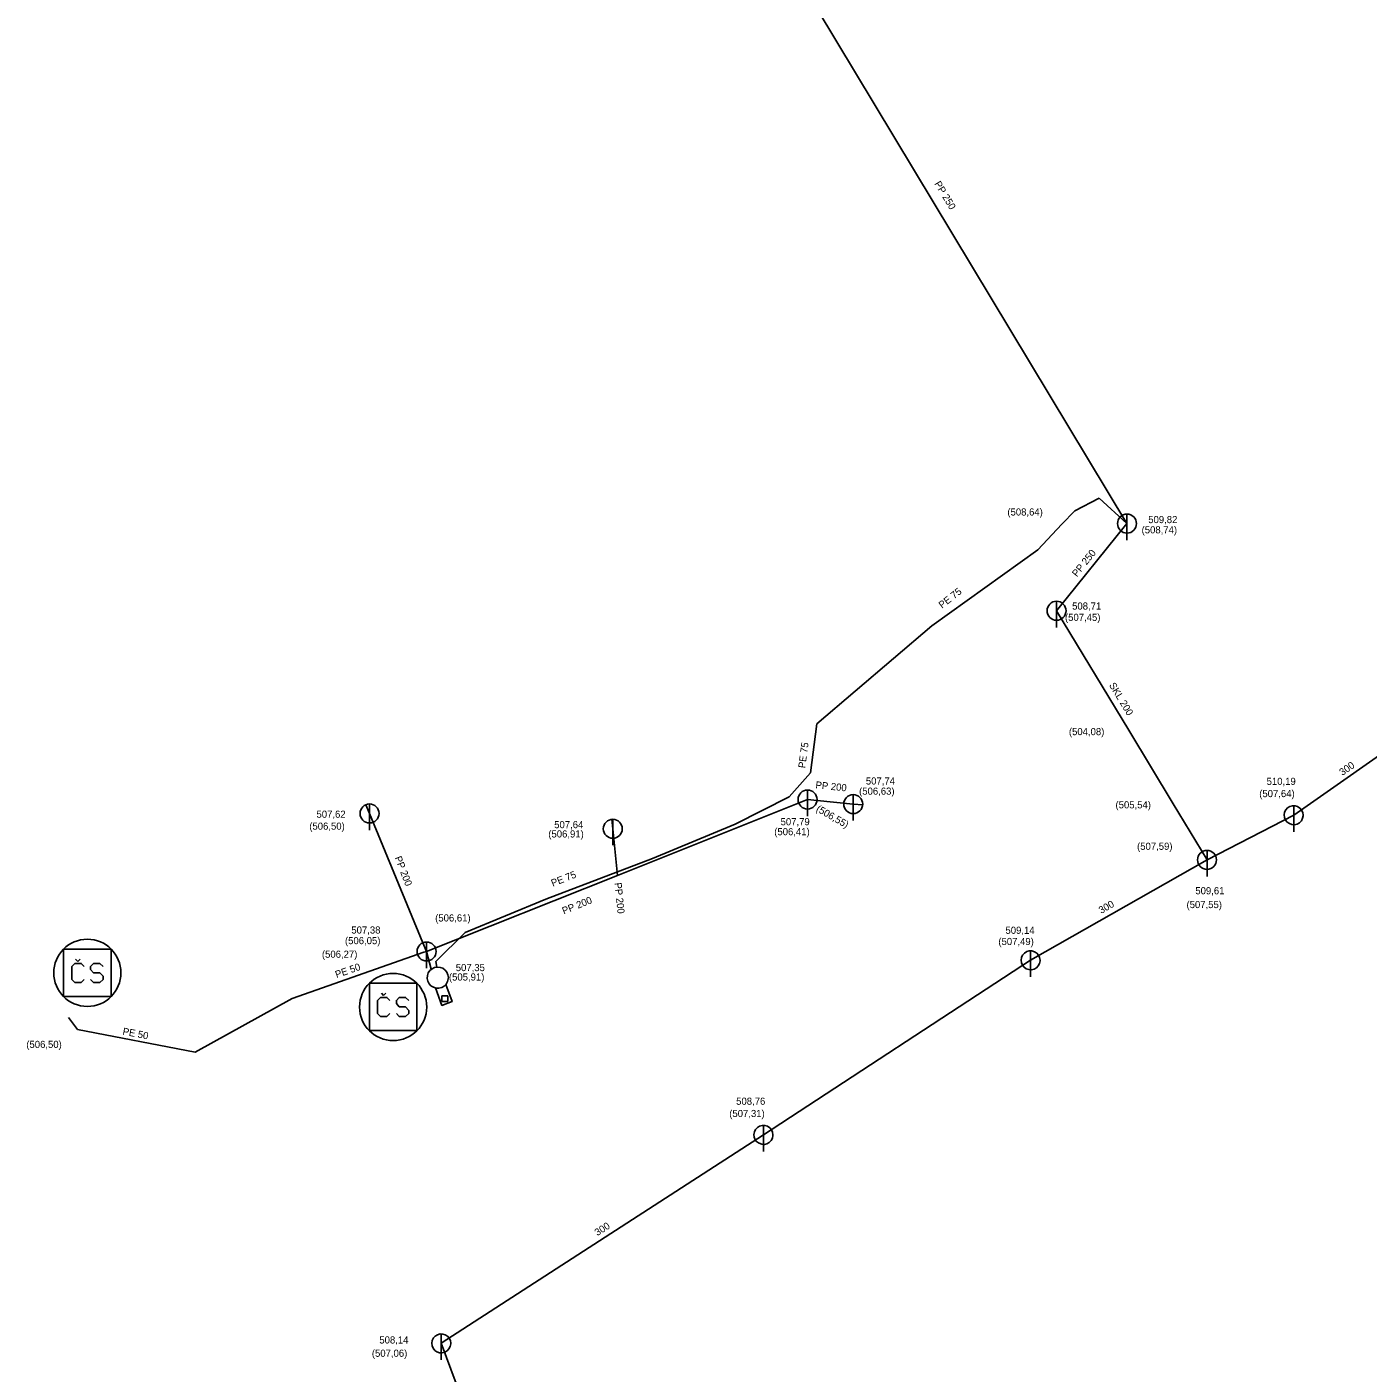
# Model space of a CAD drawing. Extents: x -476058 to -471893, y -1155786 to -1152000.
# Drawn here: x -475199.9 to -475058.6, y -1154216.9 to -1154075.1 of the extents above; entities that cross this region are included whole.
import ezdxf

# ---------------------------------------------------------------- set-up
doc = ezdxf.new("R2010")
doc.units = 0
for name, color, linetype in [('Vrstva 10', 7, 'Continuous'), ('Vrstva 11', 7, 'Continuous'), ('Vrstva 13', 7, 'Continuous'), ('Vrstva 17', 7, 'Continuous'), ('Vrstva 18', 7, 'Continuous'), ('Vrstva 19', 7, 'Continuous'), ('Vrstva 22', 7, 'Continuous'), ('Vrstva 23', 7, 'Continuous'), ('Vrstva 3', 7, 'Continuous'), ('Vrstva 4', 7, 'Continuous'), ('Vrstva 40', 7, 'Continuous'), ('Vrstva 45', 7, 'Continuous'), ('Vrstva 50', 7, 'Continuous')]:
    doc.layers.add(name, color=color, linetype=linetype)

msp = doc.modelspace()

# ---------------------------------------------------------------- linework, layer by layer
at = {"layer": 'Vrstva 10'}
for p, q in [((-475084.02, -1154126.4), (-475084.02, -1154129.14)), ((-475091.44, -1154135.58), (-475091.44, -1154138.33)), ((-475117.67, -1154155.47), (-475117.67, -1154158.21)), ((-475112.86, -1154155.95), (-475112.86, -1154158.69)), ((-475163.81, -1154156.94), (-475163.81, -1154159.69)), ((-475066.46, -1154157.12), (-475066.46, -1154159.87)), ((-475138.19, -1154158.55), (-475138.19, -1154161.29)), ((-475075.59, -1154161.83), (-475075.59, -1154164.58)), ((-475157.8, -1154171.48), (-475157.8, -1154174.23)), ((-475094.18, -1154172.41), (-475094.18, -1154175.16)), ((-475122.32, -1154190.8), (-475122.32, -1154193.55)), ((-475156.26, -1154212.76), (-475156.26, -1154215.51))]:
    msp.add_line(p, q, dxfattribs=at)
for points in [[(-475065.46, -1154158.12), (-475065.5, -1154157.84), (-475065.62, -1154157.58), (-475065.8, -1154157.37), (-475066.04, -1154157.22), (-475066.3, -1154157.13), (-475066.59, -1154157.13), (-475066.86, -1154157.2), (-475067.1, -1154157.35), (-475067.29, -1154157.56), (-475067.41, -1154157.81), (-475067.46, -1154158.09), (-475067.43, -1154158.37), (-475067.32, -1154158.63), (-475067.14, -1154158.85), (-475066.91, -1154159.01), (-475066.64, -1154159.1), (-475066.36, -1154159.12), (-475066.09, -1154159.05), (-475065.84, -1154158.91), (-475065.65, -1154158.7), (-475065.52, -1154158.45), (-475065.46, -1154158.18), (-475065.46, -1154158.12)], [(-475093.18, -1154173.41), (-475093.22, -1154173.13), (-475093.34, -1154172.87), (-475093.52, -1154172.66), (-475093.76, -1154172.51), (-475094.03, -1154172.42), (-475094.31, -1154172.42), (-475094.58, -1154172.49), (-475094.82, -1154172.64), (-475095.01, -1154172.85), (-475095.13, -1154173.1), (-475095.18, -1154173.38), (-475095.15, -1154173.66), (-475095.04, -1154173.92), (-475094.86, -1154174.14), (-475094.63, -1154174.3), (-475094.36, -1154174.39), (-475094.08, -1154174.41), (-475093.81, -1154174.34), (-475093.56, -1154174.2), (-475093.37, -1154173.99), (-475093.24, -1154173.74), (-475093.18, -1154173.47), (-475093.18, -1154173.41)], [(-475121.32, -1154191.8), (-475121.36, -1154191.52), (-475121.48, -1154191.26), (-475121.66, -1154191.05), (-475121.9, -1154190.9), (-475122.17, -1154190.81), (-475122.45, -1154190.81), (-475122.72, -1154190.88), (-475122.96, -1154191.03), (-475123.15, -1154191.24), (-475123.27, -1154191.49), (-475123.32, -1154191.77), (-475123.29, -1154192.05), (-475123.18, -1154192.31), (-475123, -1154192.53), (-475122.77, -1154192.69), (-475122.5, -1154192.78), (-475122.22, -1154192.8), (-475121.95, -1154192.73), (-475121.7, -1154192.59), (-475121.51, -1154192.38), (-475121.38, -1154192.13), (-475121.32, -1154191.86), (-475121.32, -1154191.8)], [(-475155.26, -1154213.76), (-475155.3, -1154213.48), (-475155.42, -1154213.23), (-475155.6, -1154213.01), (-475155.83, -1154212.86), (-475156.1, -1154212.78), (-475156.39, -1154212.77), (-475156.66, -1154212.85), (-475156.9, -1154212.99), (-475157.09, -1154213.2), (-475157.21, -1154213.46), (-475157.26, -1154213.74), (-475157.23, -1154214.02), (-475157.12, -1154214.28), (-475156.94, -1154214.5), (-475156.71, -1154214.66), (-475156.44, -1154214.75), (-475156.16, -1154214.76), (-475155.89, -1154214.69), (-475155.64, -1154214.55), (-475155.45, -1154214.35), (-475155.32, -1154214.1), (-475155.26, -1154213.82), (-475155.26, -1154213.76)]]:
    msp.add_lwpolyline(points, dxfattribs=at)
for centre in [(-475084.02, -1154127.4), (-475091.44, -1154136.58), (-475117.67, -1154156.47), (-475112.86, -1154156.95), (-475163.81, -1154157.94), (-475138.19, -1154159.55), (-475075.59, -1154162.83), (-475157.8, -1154172.48)]:
    msp.add_circle(centre, 1, dxfattribs=at)
at = {"layer": 'Vrstva 11'}
for p, q in [((-475196.04, -1154172.23), (-475191.04, -1154172.23)), ((-475196.04, -1154177.23), (-475196.04, -1154172.23)), ((-475191.04, -1154172.23), (-475191.04, -1154177.23)), ((-475163.83, -1154175.82), (-475158.83, -1154175.82)), ((-475163.83, -1154180.82), (-475163.83, -1154175.82)), ((-475158.83, -1154175.82), (-475158.83, -1154180.82)), ((-475191.04, -1154177.23), (-475196.04, -1154177.23)), ((-475158.83, -1154180.82), (-475163.83, -1154180.82))]:
    msp.add_line(p, q, dxfattribs=at)
for points in [[(-475193.86, -1154175.42), (-475194.19, -1154175.73), (-475194.85, -1154175.73), (-475195.17, -1154175.42), (-475195.17, -1154174.05), (-475194.85, -1154173.73), (-475194.19, -1154173.73), (-475193.86, -1154174.05)], [(-475194.54, -1154173.53), (-475194.78, -1154173.29)], [(-475194.54, -1154173.53), (-475194.3, -1154173.29)], [(-475193.2, -1154175.42), (-475192.89, -1154175.73), (-475192.23, -1154175.73), (-475191.89, -1154175.42), (-475191.89, -1154175.09), (-475192.23, -1154174.73), (-475192.89, -1154174.73), (-475193.2, -1154174.38), (-475193.2, -1154174.05), (-475192.89, -1154173.73), (-475192.23, -1154173.73), (-475191.89, -1154174.05)], [(-475161.66, -1154179.01), (-475161.99, -1154179.32), (-475162.65, -1154179.32), (-475162.96, -1154179.01), (-475162.96, -1154177.64), (-475162.65, -1154177.32), (-475161.99, -1154177.32), (-475161.66, -1154177.64)], [(-475162.33, -1154177.12), (-475162.57, -1154176.88)], [(-475162.33, -1154177.12), (-475162.1, -1154176.88)], [(-475160.99, -1154179.01), (-475160.68, -1154179.32), (-475160.02, -1154179.32), (-475159.69, -1154179.01), (-475159.69, -1154178.68), (-475160.02, -1154178.32), (-475160.68, -1154178.32), (-475160.99, -1154177.97), (-475160.99, -1154177.64), (-475160.68, -1154177.32), (-475160.02, -1154177.32), (-475159.69, -1154177.64)]]:
    msp.add_lwpolyline(points, dxfattribs=at)
for centre in [(-475193.54, -1154174.73), (-475161.33, -1154178.33)]:
    msp.add_circle(centre, 3.54, dxfattribs=at)
at = {"layer": 'Vrstva 13'}
for p, q in [((-475155.58, -1154177.14), (-475156.18, -1154177.14)), ((-475156.18, -1154177.14), (-475156.18, -1154177.74)), ((-475156.18, -1154177.74), (-475155.58, -1154177.74)), ((-475155.58, -1154177.74), (-475155.58, -1154177.14))]:
    msp.add_line(p, q, dxfattribs=at)
at = {"layer": 'Vrstva 22'}
msp.add_lwpolyline([(-475155.51, -1154175.23), (-475155.55, -1154174.94), (-475155.67, -1154174.66), (-475155.85, -1154174.43), (-475156.09, -1154174.25), (-475156.37, -1154174.15), (-475156.67, -1154174.12), (-475156.96, -1154174.17), (-475157.23, -1154174.29), (-475157.46, -1154174.49), (-475157.62, -1154174.74), (-475157.72, -1154175.02), (-475157.74, -1154175.31), (-475157.67, -1154175.61), (-475157.54, -1154175.87), (-475157.34, -1154176.09), (-475157.08, -1154176.25), (-475156.8, -1154176.33), (-475156.5, -1154176.34), (-475156.21, -1154176.27), (-475155.95, -1154176.12), (-475155.74, -1154175.91), (-475155.59, -1154175.65), (-475155.52, -1154175.36), (-475155.51, -1154175.23)], dxfattribs=at)
at = {"layer": 'Vrstva 23'}
msp.add_lwpolyline([(-475156.88, -1154176.32), (-475156.18, -1154178.16), (-475155.12, -1154177.75), (-475155.78, -1154175.96)], dxfattribs=at)
at = {"layer": 'Vrstva 40'}
for p, q in [((-475086.94, -1154124.71), (-475084.02, -1154127.4)), ((-475104.57, -1154138.17), (-475093.41, -1154130.15)), ((-475091.44, -1154136.58), (-475083.84, -1154149.15)), ((-475116.68, -1154148.49), (-475104.57, -1154138.17)), ((-475117.37, -1154153.65), (-475116.68, -1154148.49)), ((-475083.84, -1154149.15), (-475079.16, -1154156.91)), ((-475119.6, -1154156.2), (-475117.37, -1154153.65)), ((-475125.29, -1154159.05), (-475119.6, -1154156.2)), ((-475079.16, -1154156.91), (-475075.59, -1154162.83)), ((-475134, -1154162.68), (-475125.29, -1154159.05)), ((-475145.25, -1154166.95), (-475134, -1154162.68)), ((-475153.74, -1154170.48), (-475145.25, -1154166.95))]:
    msp.add_line(p, q, dxfattribs=at)
for points in [[(-475118.72, -1154069.74), (-475084.02, -1154127.4)], [(-475093.41, -1154130.15), (-475090.87, -1154127.47), (-475089.53, -1154126.04), (-475086.94, -1154124.71)], [(-475084.02, -1154127.4), (-475091.44, -1154136.58)], [(-475117.67, -1154156.47), (-475137.68, -1154164.47)], [(-475137.68, -1154164.47), (-475157.8, -1154172.48)], [(-475156.72, -1154174.12), (-475156.84, -1154173.54), (-475153.74, -1154170.48)], [(-475157.8, -1154172.48), (-475157.31, -1154174.35)]]:
    msp.add_lwpolyline(points, dxfattribs=at)
at = {"layer": 'Vrstva 45'}
for points in [[(-475053.57, -1154149.1), (-475066.46, -1154158.12)], [(-475066.46, -1154158.12), (-475075.59, -1154162.83)], [(-475075.59, -1154162.83), (-475094.18, -1154173.41)], [(-475094.18, -1154173.41), (-475122.32, -1154191.8)], [(-475122.32, -1154191.8), (-475156.26, -1154213.76)], [(-475156.26, -1154213.76), (-475150.39, -1154229.5)]]:
    msp.add_lwpolyline(points, dxfattribs=at)
at = {"layer": 'Vrstva 50'}
for points in [[(-475111.86, -1154157.04), (-475112.86, -1154156.95), (-475116.67, -1154156.56), (-475117.67, -1154156.47)], [(-475164.2, -1154157.02), (-475163.81, -1154157.94), (-475158.19, -1154171.56), (-475157.8, -1154172.48)], [(-475138.29, -1154158.55), (-475138.19, -1154159.55), (-475137.68, -1154164.47)], [(-475195.54, -1154179.44), (-475194.57, -1154180.69), (-475182.2, -1154183.07), (-475171.96, -1154177.44), (-475158.11, -1154172.56)], [(-475158.11, -1154172.56), (-475157.8, -1154172.48)]]:
    msp.add_lwpolyline(points, dxfattribs=at)

# ---------------------------------------------------------------- texts
at = {"layer": 'Vrstva 17'}
for s, rotation, p in [('PP 250', 301.035, (-475104.34, -1154091.59)), ('PP 250', 51.062, (-475089.3, -1154133.07)), ('PE 75', 38.2319, (-475103.5, -1154136.38)), ('SKL 200', 301.1252, (-475085.94, -1154144.42)), ('PE 75', 82.4235, (-475117.92, -1154153.2)), ('PE 75', 21.5533, (-475144.51, -1154165.66)), ('PP 200', 21.7926, (-475143.35, -1154168.58))]:
    msp.add_text(s, height=0.75, rotation=rotation, dxfattribs=at).set_placement(p)
at = {"layer": 'Vrstva 18'}
for rotation, p in [(34.9831, (-475061.33, -1154153.99)), (29.6439, (-475086.74, -1154168.53)), (32.7753, (-475139.81, -1154202.48))]:
    msp.add_text('300 ', height=0.75, rotation=rotation, dxfattribs=at).set_placement(p)
at = {"layer": 'Vrstva 19'}
for s, rotation, p in [('PP 200', 354.2929, (-475116.86, -1154155.29)), ('PP 200', 291.1662, (-475161.18, -1154162.6)), ('PP 200', 275.8708, (-475138.01, -1154165.26)), ('PE 50', 19.145, (-475167.28, -1154175.29)), ('PE 50', 349.1253, (-475189.87, -1154181.23))]:
    msp.add_text(s, height=0.75, rotation=rotation, dxfattribs=at).set_placement(p)
at = {"layer": 'Vrstva 3'}
for s, p in [('509,82', (-475081.78, -1154127.35)), ('508,71', (-475089.8, -1154136.46)), ('507,74', (-475111.53, -1154154.89)), ('510,19', (-475069.31, -1154154.93)), ('507,62', (-475169.4, -1154158.39)), ('507,64', (-475144.36, -1154159.49)), ('507,79', (-475120.51, -1154159.18)), ('509,61', (-475076.82, -1154166.45)), ('507,38', (-475165.73, -1154170.59)), ('509,14', (-475096.82, -1154170.62)), ('507,35', (-475154.73, -1154174.55)), ('508,76', (-475125.19, -1154188.63)), ('508,14', (-475162.78, -1154213.78))]:
    msp.add_text(s, height=0.75, dxfattribs=at).set_placement(p)
at = {"layer": 'Vrstva 4'}
for s, p in [('(508,64)', (-475096.62, -1154126.55)), ('(508,74)', (-475082.48, -1154128.43)), ('(507,45)', (-475090.55, -1154137.65)), ('(504,08)', (-475090.14, -1154149.69)), ('(506,63)', (-475112.24, -1154155.96)), ('(505,54)', (-475085.23, -1154157.4)), ('(507,64)', (-475070.09, -1154156.22)), ('(506,50)', (-475170.16, -1154159.65)), ('(506,41)', (-475121.18, -1154160.23)), ('(506,91)', (-475144.98, -1154160.47)), ('(507,59)', (-475082.96, -1154161.77)), ('(507,55)', (-475077.75, -1154167.91)), ('(506,61)', (-475156.9, -1154169.32)), ('(506,05)', (-475166.4, -1154171.71)), ('(507,49)', (-475097.57, -1154171.8)), ('(506,27)', (-475168.83, -1154173.14)), ('(505,91)', (-475155.45, -1154175.54)), ('(506,50)', (-475199.97, -1154182.64)), ('(507,31)', (-475125.92, -1154189.92)), ('(507,06)', (-475163.57, -1154215.18))]:
    msp.add_text(s, height=0.75, dxfattribs=at).set_placement(p)
msp.add_text('(506,55)', height=0.75, rotation=330, dxfattribs=at).set_placement((-475116.84, -1154157.65))

doc.saveas('drawing.dxf')
